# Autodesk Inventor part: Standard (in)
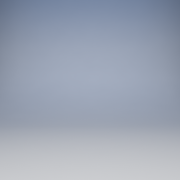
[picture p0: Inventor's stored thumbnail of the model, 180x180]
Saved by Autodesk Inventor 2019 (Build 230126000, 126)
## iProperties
Created: 2018-02
Part Number: Standard (in)
Material: Všeobecné
Document SubType Name: Modeling
Density: 1 g/cm^3
Appearance: Výchozí
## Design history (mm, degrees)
